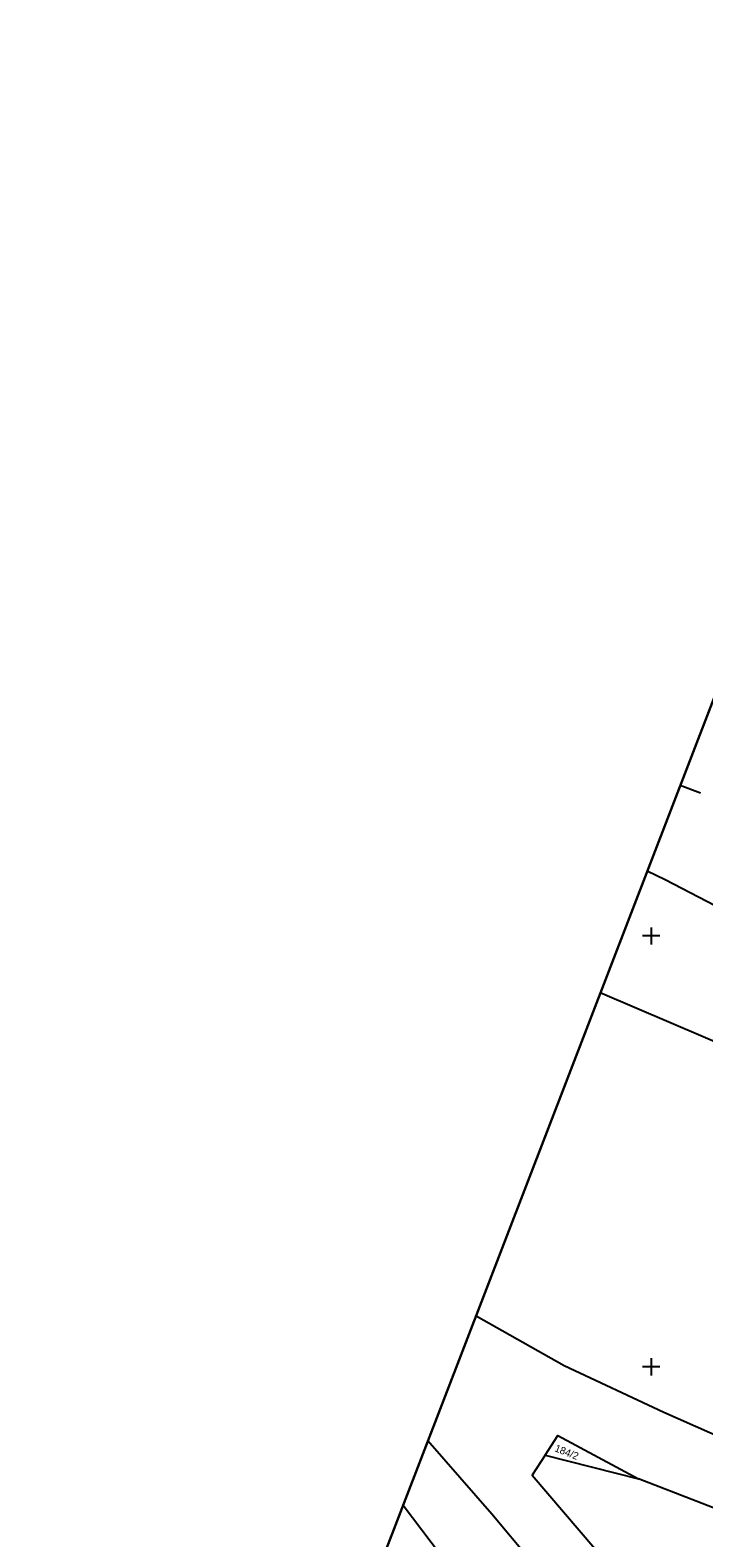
# Model space of a CAD drawing. Extents: x -755344 to -754413, y -1162670 to -1161477.
# Drawn here: x -755344.1 to -755187.8, y -1162239.7 to -1161889.7 of the extents above; entities that cross this region are included whole.
import ezdxf

# ---------------------------------------------------------------- set-up
doc = ezdxf.new("R2010")
doc.units = 0
for name, color, linetype in [('Formát', 7, 'Continuous'), ('Síť', 7, 'Continuous'), ('Vrstva 55', 7, 'Continuous'), ('Vrstva 57', 7, 'Continuous')]:
    doc.layers.add(name, color=color, linetype=linetype)

msp = doc.modelspace()

# ---------------------------------------------------------------- linework, layer by layer
at = {"layer": 'Formát'}
for p, q in [((-755042.37, -1161673.02), (-755344.08, -1162456.97)), ((-755042.37, -1161673.02), (-755344.08, -1162456.97)), ((-755193.22, -1162065), (-755188.56, -1162066.79))]:
    msp.add_line(p, q, dxfattribs=at)
msp.add_lwpolyline([(-754488.01, -1161886.37), (-754789.71, -1162670.32), (-755344.08, -1162456.97), (-755042.37, -1161673.02)], close=True, dxfattribs=at)
msp.add_lwpolyline([(-754789.71, -1162670.32), (-754488.01, -1161886.37), (-755042.37, -1161673.02), (-755344.08, -1162456.97)], dxfattribs=at)
at = {"layer": 'Síť'}
for points in [[(-755200, -1162098), (-755200, -1162100), (-755200, -1162102)], [(-755198, -1162100), (-755200, -1162100), (-755202, -1162100)], [(-755198, -1162200), (-755200, -1162200), (-755202, -1162200)], [(-755200, -1162198), (-755200, -1162200), (-755200, -1162202)]]:
    msp.add_lwpolyline(points, dxfattribs=at)
at = {"layer": 'Vrstva 55'}
msp.add_line((-755224.59, -1162220.51), (-755202.91, -1162226.05), dxfattribs=at)
for points in [[(-755200.88, -1162084.9), (-755196.74, -1162086.92), (-755095.99, -1162139.26)], [(-755098.17, -1162163.16), (-755171.47, -1162130.42), (-755211.78, -1162113.21)], [(-755240.62, -1162188.15), (-755220.18, -1162199.71), (-755197.03, -1162210.54), (-755175.66, -1162219.97), (-755153.09, -1162227.31), (-755128.84, -1162232.93), (-755106.85, -1162236.16)], [(-755251.78, -1162217.14), (-755236.92, -1162234.12), (-755218.86, -1162255.78), (-755201.65, -1162278.82), (-755185.6, -1162302.84), (-755168.69, -1162327.53), (-755155.26, -1162350.62), (-755154.66, -1162351.82), (-755141.68, -1162377.77), (-755128.84, -1162403.34)], [(-755224.59, -1162220.51), (-755221.65, -1162215.97), (-755202.91, -1162226.05)], [(-755224.59, -1162220.51), (-755227.6, -1162225.16), (-755213.03, -1162242.21), (-755197.95, -1162261.69), (-755179.66, -1162287.01), (-755159.89, -1162316.68), (-755155.21, -1162323.55), (-755152.98, -1162327.62)], [(-755140.31, -1162246.01), (-755156.59, -1162242.36), (-755179.53, -1162235.08), (-755202.91, -1162226.05)], [(-755257.56, -1162232.16), (-755228.92, -1162270), (-755211.8, -1162300.42), (-755208.54, -1162317.82)]]:
    msp.add_lwpolyline(points, dxfattribs=at)

# ---------------------------------------------------------------- texts
at = {"layer": 'Vrstva 57'}
msp.add_text('184/2', height=1.7, rotation=338.4561, dxfattribs=at).set_placement((-755222.53, -1162219.57))

doc.saveas('drawing.dxf')
